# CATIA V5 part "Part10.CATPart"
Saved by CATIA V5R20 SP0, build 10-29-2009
Part number: 1DIN7991416_DIN 7991 - M4 x 16 --- 16C
Revision: ANY
Definition: UNKNOWN
Nomenclature: 1DIN7991416_DIN 7991 - M4 x 16 --- 16C
Source: Unknown
Bounding box of the stored display mesh (mm): x 0 to 16, y -3.633 to 3.633, z -3.82 to 3.82
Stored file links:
  C:\Users\Utente\Desktop\IO LAVORO\3D X SITO CF\CUMSA\3D files PW\pw060830\pw060830_injection\Part10.CATPart
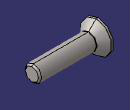
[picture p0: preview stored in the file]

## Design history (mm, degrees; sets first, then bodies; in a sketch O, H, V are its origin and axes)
Body1 "Hex" (main body)
  Solid1: solid without history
